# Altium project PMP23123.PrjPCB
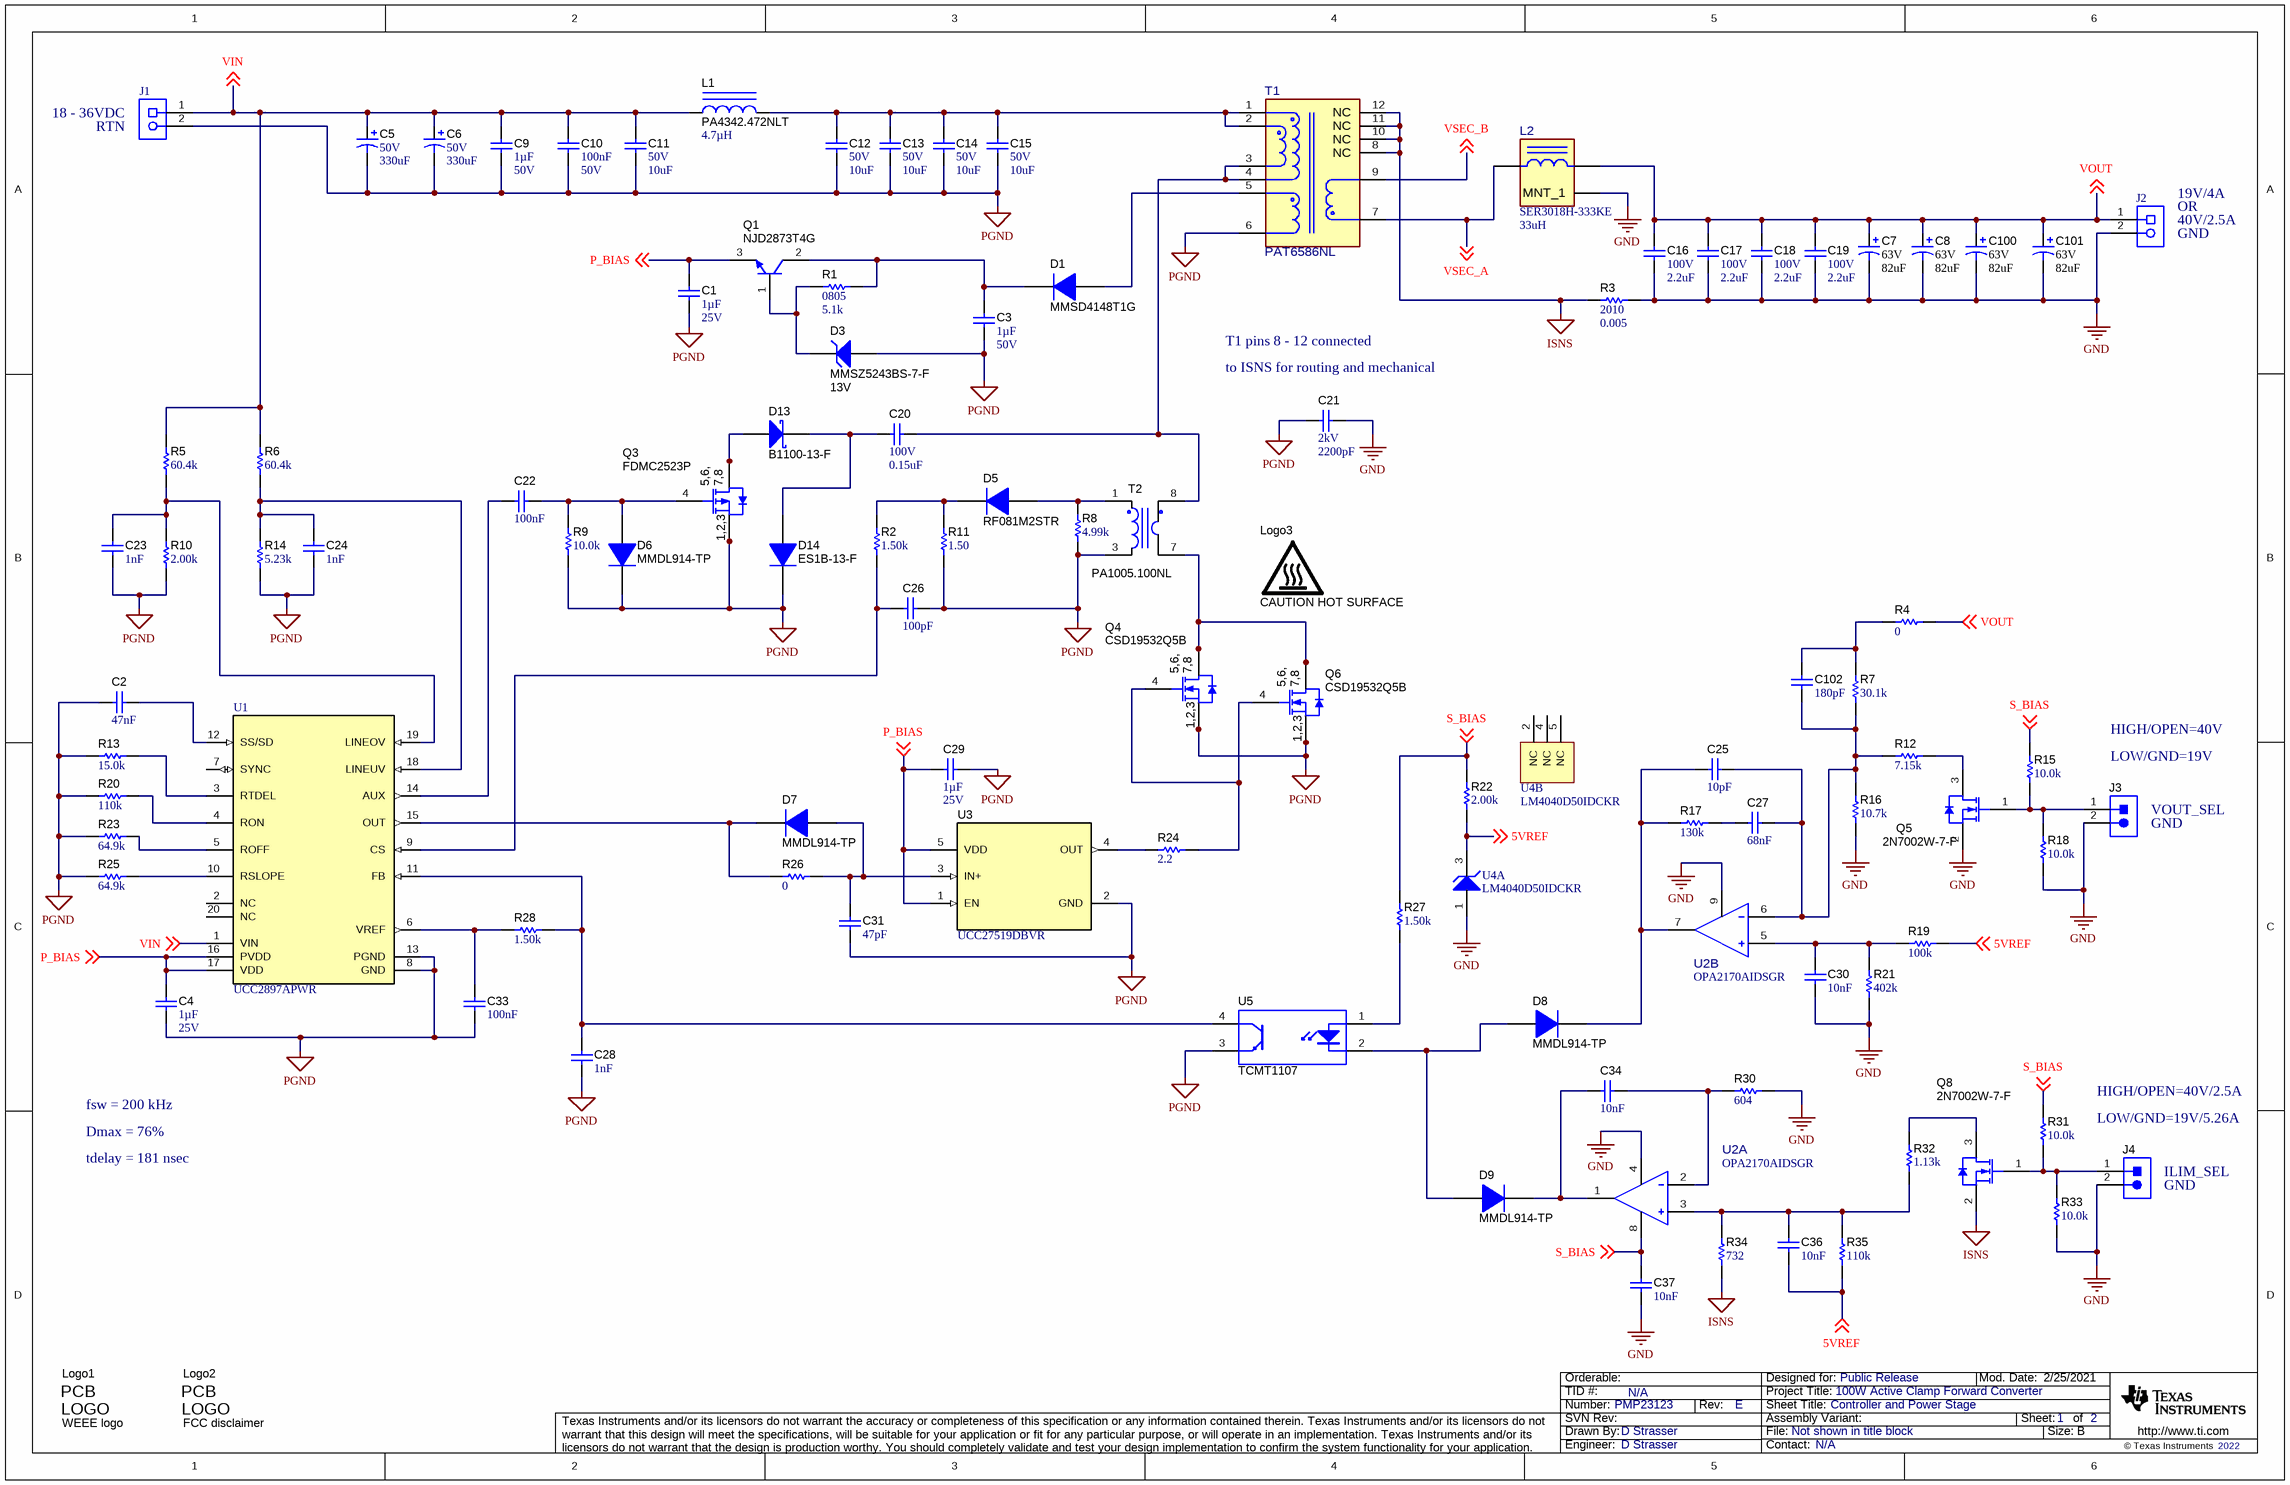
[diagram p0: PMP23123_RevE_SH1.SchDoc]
CopyrightYear: 2022; PCB_Layout: D Strasser; PCB_Rev: E; PRJ_Customer: Public Release; PRJ_Engineer: D Strasser; PRJ_Number: PMP23123; PRJ_Title: 100W Active Clamp Forward Converter; SCH_Rev: E; TechSupport: N/A; TID: N/A
2 sheets, 128 parts. Net scope: global (net labels, ports and power ports of the same name join across sheets).
Board file: PMP23123_RevE.PcbDoc
Sheets:
  PMP23123_RevE_SH1.SchDoc
  PMP23123_RevE_SH2.SchDoc

## Sheet PMP23123_RevE_SH1.SchDoc: Controller and Power Stage
size 431 x 279 mm; Date: Not shown in title block; ApprovedBy: Not shown in title block; CheckedBy: Not shown in title block; Author: Not shown in title block; CompanyName: Not shown in title block; DrawnBy: D Strasser; Engineer: Not shown in title block; Organization: Not shown in title block; Address1: Not shown in title block; Address2: Not shown in title block; Address3: Not shown in title block; Address4: Not shown in title block; DocumentNumber: 1; Revision: Use project parameter SCH_Rev; SheetNumber: 1; SheetTotal: 2; PageSetup: Record=PageOptions¦CenterHorizontal=True¦CenterVertical=True¦PrintScale=1.00¦XCorrection=1.00¦YCorrection=1.00¦PrintKind=0¦BorderSize=5000000¦LeftOffset=0¦BottomOffset=0¦Orientation=2¦PaperLength=1000¦PaperWidth=1000¦Scale=100¦PaperSource=15¦PrintQuality=600¦MediaType=1¦DitherType=10¦PaperKind=Letter¦PrintScaleMode=1

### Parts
C1  Cap_F: 1µF  VDC_V: 25V  [0603L]  (hidden comment: C0603C105K3RACTU)
C2  Cap_F: 47nF  [0603L]  (hidden comment: GRM188R71E473KA01D)
C3  Cap_F: 1µF  VDC_V: 50V  [0805_HV]  (hidden comment: C0805C105K5RACTU)
C4  Cap_F: 1µF  VDC_V: 25V  [0603L]  (hidden comment: C0603C105K3RACTU)
C5  VDC_V: 50V  ValueDisplayed: 330uF  [SM_RADIAL_H13]  (hidden comment: EEV-FK1H331Q)
C6  VDC_V: 50V  ValueDisplayed: 330uF  [SM_RADIAL_H13]  (hidden comment: EEV-FK1H331Q)
C7  VDC_V: 63V  ValueDisplayed: 82uF  [SM_RADIAL_10BMM]  (hidden comment: HHXD630ARA820MJA0G)
C8  VDC_V: 63V  ValueDisplayed: 82uF  [SM_RADIAL_10BMM]  (hidden comment: HHXD630ARA820MJA0G)
C9  Cap_F: 1µF  VDC_V: 50V  [0805_HV]  (hidden comment: C0805C105K5RACTU)
C10  Cap_F: 100nF  VDC_V: 50V  [0603]  (hidden comment: C0603C104K5RACTU)
C11  VDC_V: 50V  ValueDisplayed: 10uF  [1210_280]  (hidden comment: UMK325AB7106KM-T)
C12  VDC_V: 50V  ValueDisplayed: 10uF  [1210_280]  (hidden comment: UMK325AB7106KM-T)
C13  VDC_V: 50V  ValueDisplayed: 10uF  [1210_280]  (hidden comment: UMK325AB7106KM-T)
C14  VDC_V: 50V  ValueDisplayed: 10uF  [1210_280]  (hidden comment: UMK325AB7106KM-T)
C15  VDC_V: 50V  ValueDisplayed: 10uF  [1210_280]  (hidden comment: UMK325AB7106KM-T)
C16  VDC_V: 100V  ValueDisplayed: 2.2uF  [1210_210]  (hidden comment: C1210C225K1RACTU)
C17  VDC_V: 100V  ValueDisplayed: 2.2uF  [1210_210]  (hidden comment: C1210C225K1RACTU)
C18  VDC_V: 100V  ValueDisplayed: 2.2uF  [1210_210]  (hidden comment: C1210C225K1RACTU)
C19  VDC_V: 100V  ValueDisplayed: 2.2uF  [1210_210]  (hidden comment: C1210C225K1RACTU)
C20  VDC_V: 100V  ValueDisplayed: 0.15uF  [1206]  (hidden comment: GRM31MR72A154KA01L)
C21  VDC_V: 2kV  ValueDisplayed: 2200pF  [1812_HV]  (hidden comment: C4532X7R3D222K130KA)
C22  Cap_F: 100nF  [0603L]  (hidden comment: 885012206071)
C23  Cap_F: 1nF  [0603L]  (hidden comment: 885012206083)
C24  Cap_F: 1nF  [0603L]  (hidden comment: 885012206083)
C25  ValueDisplayed: 10pF  [0603L]  (hidden comment: C0603C100J5GACTU)
C26  ValueDisplayed: 100pF  [0603]  (hidden comment: 885012006057)
C27  Cap_F: 68nF  [0603L]  (hidden comment: 885012206070)
C28  Cap_F: 1nF  [0603L]  (hidden comment: 885012206083)
C29  Cap_F: 1µF  VDC_V: 25V  [0603L]  (hidden comment: C0603C105K3RACTU)
C30  Cap_F: 10nF  [0603L]  (hidden comment: C0603C103K5RACTU)
C31  ValueDisplayed: 47pF  [0603L]  (hidden comment: C0603C470J5GACTU)
C33  Cap_F: 100nF  [0603L]  (hidden comment: 885012206071)
C34  Cap_F: 10nF  [0603L]  (hidden comment: C0603C103K5RACTU)
C36  Cap_F: 10nF  [0603L]  (hidden comment: C0603C103K5RACTU)
C37  Cap_F: 10nF  [0603L]  (hidden comment: C0603C103K5RACTU)
C100  VDC_V: 63V  ValueDisplayed: 82uF  [SM_RADIAL_10BMM]  (hidden comment: HHXD630ARA820MJA0G)
C101  VDC_V: 63V  ValueDisplayed: 82uF  [SM_RADIAL_10BMM]  (hidden comment: HHXD630ARA820MJA0G)
C102  ValueDisplayed: 180pF  [0603L]  (hidden comment: C0603C181J5GACTU)
D1  MMSD4148T1G  [SOD-123]
D3  MMSZ5243BS-7-F  value 13V  [SOD-323]
D5  RF081M2STR  [SOD-123]
D6  MMDL914-TP  [SOD-323]
D7  MMDL914-TP  [SOD-323]
D8  MMDL914-TP  [SOD-323]
D9  MMDL914-TP  [SOD-323]
D13  B1100-13-F  [SMA]
D14  ES1B-13-F  [SMA]
J1  691236510002  [Wurth_691236510002]  (value not drawn)
J2  691236510002  [Wurth_691236510002]  (value not drawn)
J3  TSW-102-07-G-S  [TSW-102-07-G-S]  (value not drawn)
J4  TSW-102-07-G-S  [TSW-102-07-G-S]  (value not drawn)
L1  PA4342.472NLT  ValueDisplayed: 4.7µH  [PA4342_2]
L2  value 33uH  [FP-SER3018H-333KE_SMT3_27MM94_27MM94-MFG]  (hidden comment: SER3018H-333KE)
Logo1  WEEE logo  [WEEE_Minimum]  (no BOM)
Logo2  FCC disclaimer  [FCC_disclaimer]  (no BOM)
Logo3  CAUTION HOT SURFACE  [IEC_HotSurface_Small]  (no BOM)
Q1  NJD2873T4G  [DPAK]
Q3  FDMC2523P  [MLP08S]
Q4  CSD19532Q5B  [DNK0008A]
Q5  2N7002W-7-F  [SOT-323]
Q6  CSD19532Q5B  [DNK0008A]
Q8  2N7002W-7-F  [SOT-323]
R1  PackageReference: 0805  ValueDisplayed: 5.1k  [0805_HV]  (hidden comment: CRCW08055K10JNEA)
R2  ValueDisplayed: 1.50k  [0603L]  (hidden comment: CRCW06031K50FKEA)
R3  ValueDisplayed: 0.005  [2010]  (hidden comment: WSL20105L000FEA)
R4  ValueDisplayed: 0  [0603L]  (hidden comment: CRCW06030000Z0EA)
R5  ValueDisplayed: 60.4k  [0603L]  (hidden comment: CRCW060360K4FKEA)
R6  ValueDisplayed: 60.4k  [0603L]  (hidden comment: CRCW060360K4FKEA)
R7  ValueDisplayed: 30.1k  [0603L]  (hidden comment: CRCW060330K1FKEA)
R8  ValueDisplayed: 4.99k  [0603L]  (hidden comment: CRCW06034K99FKEA)
R9  ValueDisplayed: 10.0k  [0603L]  (hidden comment: CRCW060310K0FKEA)
R10  ValueDisplayed: 2.00k  [0603L]  (hidden comment: CRCW06032K00FKEA)
R11  ValueDisplayed: 1.50  [0603L]  (hidden comment: CRCW06031R50FKEA)
R12  ValueDisplayed: 7.15k  [0603L]  (hidden comment: CRCW06037K15FKEA)
R13  ValueDisplayed: 15.0k  [0603L]  (hidden comment: CRCW060315K0FKEA)
R14  ValueDisplayed: 5.23k  [0603L]  (hidden comment: CRCW06035K23FKEA)
R15  ValueDisplayed: 10.0k  [0603L]  (hidden comment: CRCW060310K0FKEA)
R16  ValueDisplayed: 10.7k  [0603L]  (hidden comment: CRCW060310K7FKEA)
R17  ValueDisplayed: 130k  [0603L]  (hidden comment: CRCW0603130KFKEA)
R18  ValueDisplayed: 10.0k  [0603L]  (hidden comment: CRCW060310K0FKEA)
R19  ValueDisplayed: 100k  [0603L]  (hidden comment: CRCW0603100KFKEA)
R20  ValueDisplayed: 110k  [0603L]  (hidden comment: CRCW0603110KFKEA)
R21  ValueDisplayed: 402k  [0603L]  (hidden comment: CRCW0603402KFKEA)
R22  ValueDisplayed: 2.00k  [0603L]  (hidden comment: CRCW06032K00FKEA)
R23  ValueDisplayed: 64.9k  [0603L]  (hidden comment: CRCW060364K9FKEA)
R24  ValueDisplayed: 2.2  [0603L]  (hidden comment: CRCW06032R20JNEA)
R25  ValueDisplayed: 64.9k  [0603L]  (hidden comment: CRCW060364K9FKEA)
R26  ValueDisplayed: 0  [0603L]  (hidden comment: CRCW06030000Z0EA)
R27  ValueDisplayed: 1.50k  [0603L]  (hidden comment: CRCW06031K50FKEA)
R28  ValueDisplayed: 1.50k  [0603L]  (hidden comment: CRCW06031K50FKEA)
R30  ValueDisplayed: 604  [0603L]  (hidden comment: CRCW0603604RFKEA)
R31  ValueDisplayed: 10.0k  [0603L]  (hidden comment: CRCW060310K0FKEA)
R32  ValueDisplayed: 1.13k  [0603L]  (hidden comment: CRCW06031K13FKEA)
R33  ValueDisplayed: 10.0k  [0603L]  (hidden comment: CRCW060310K0FKEA)
R34  ValueDisplayed: 732  [0603L]  (hidden comment: CRCW0603732RFKEA)
R35  ValueDisplayed: 110k  [0603L]  (hidden comment: CRCW0603110KFKEA)
T1  PAT6586NL  [FP-PAT6586NL_SMT_XFRMR_27MM1_26MM42-MFG]
T2  PA1005.100NL  [P82xx]
U1  UCC2897APWR  [PW0020A_N]
U2  OPA2170AIDSGR  [DSG0008A-MFG]  (parts A,B of 2)
U3  UCC27519DBVR  [DBV0005A_N]
U4  LM4040D50IDCKR  [DCK0005A_N]  (parts A,B of 2)
U5  TCMT1107  [SOP-4]

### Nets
GND: C7.2(-) C8.2(-) C16.1 C17.1 C18.1 C19.1 C21.1 C30.2 C37.1 C100.2(-) C101.2(-) J2.2 J3.2 J4.2 L2.1(MNT_1) Q5.2(S) R3.2 R16.2 R18.2 R21.2 R30.2 R33.2 U2.4(V-) U2.9(Thermal_Pad) U4.1(ANODE)
ISNS: Q8.2(S) R3.1 R34.2 T1.8(NC) T1.10(NC) T1.11(NC) T1.12(NC)
PGND: C1.1 C2.2 C3.1 C4.1 C5.2(-) C6.2(-) C9.1 C10.1 C11.1 C12.1 C13.1 C14.1 C15.1 C21.2 C23.1 C24.1 C26.1 C28.1 C29.2 C31.2 C33.1 D3.2(A) D6.1(K) D14.1(K) J1.2 Q3.1(S) Q3.2(S) Q3.3(S) Q4.1(S) Q4.2(S) Q4.3(S) Q6.1(S) Q6.2(S) Q6.3(S) R8.1 R9.2 R10.2 R11.2 R13.2 R14.2 R20.1 R23.1 R25.1 T1.6 T2.3 U1.8(GND) U1.13(PGND) U3.2(GND) U5.3(E)
5VREF: C36.2 R19.2 R22.2 R35.1 U4.3(CATHODE) ; off-sheet 5VREF
P_BIAS: C1.2 C4.2 C29.1 Q1.3(E) U1.16(PVDD) U1.17(VDD) U3.1(EN) U3.5(VDD) ; off-sheet P_BIAS
S_BIAS: C37.2 R15.1 R22.1 R27.1 R31.1 U2.8(V+) ; off-sheet S_BIAS
VIN: C5.1(+) C6.1(+) C9.2 C10.2 C11.2 J1.1 L1.1 R5.2 R6.2 U1.1(VIN) ; off-sheet VIN
VOUT: C7.1(+) C8.1(+) C16.2 C17.2 C18.2 C19.2 C100.1(+) C101.1(+) J2.1 L2.3 R4.2 ; off-sheet VOUT
VSEC_A: L2.2 T1.7 ; off-sheet VSEC_A
VSEC_B: T1.9 ; off-sheet VSEC_B
NetC2_1: C2.1 U1.12(SS/SD)
NetC3_2: C3.2 D1.1(K) Q1.2(C) R1.2
NetC12_2: C12.2 C13.2 C14.2 C15.2 L1.2 T1.1 T1.2
NetC20_1: C20.1 T1.3 T1.4 T2.8
NetC20_2: C20.2 D13.1(K) D14.2(A)
NetC22_1: C22.1 D6.2(A) Q3.4(G) R9.1
NetC22_2: C22.2 U1.14(AUX)
NetC23_2: C23.2 R5.1 R10.1 U1.19(LINEOV)
NetC24_2: C24.2 R6.1 R14.1 U1.18(LINEUV)
NetC25_1: C25.1 C27.1 C102.1 R7.2 R12.1 R16.1 U2.6(-IN_B)
NetC25_2: C25.2 D8.1(K) R17.1 U2.7(OUT_B)
NetC26_2: C26.2 R2.2 U1.9(CS)
NetC27_2: C27.2 R17.2
NetC28_2: C28.2 R28.1 U1.11(FB) U5.4(C)
NetC30_1: C30.1 R19.1 R21.1 U2.5(+IN_B)
NetC31_1: C31.1 D7.2(A) R26.2 U3.3(IN+)
NetC33_2: C33.2 R28.2 U1.6(VREF)
NetC34_1: C34.1 R30.1 U2.2(-IN_A)
NetC34_2: C34.2 D9.1(K) U2.1(OUT_A)
NetC36_1: C36.1 R32.2 R34.1 R35.2 U2.3(+IN_A)
NetC102_2: C102.2 R4.1 R7.1
NetD1_2: D1.2(A) T1.5
NetD3_1: D3.1(K) Q1.1(B) R1.1
NetD5_1: D5.1(K) R2.1 R11.1
NetD5_2: D5.2(A) R8.2 T2.1
NetD7_1: D7.1(K) R26.1 U1.15(OUT)
NetD8_2: D8.2(A) D9.2(A) U5.2(K)
NetD13_2: D13.2(A) Q3.5(D) Q3.6(D) Q3.7(D) Q3.8(D)
NetJ3_1: J3.1 Q5.1(G) R15.2 R18.1
NetJ4_1: J4.1 Q8.1(G) R31.2 R33.1
NetQ4_4: Q4.4(G) Q6.4(G) R24.1
NetQ4_5: Q4.5(D) Q4.6(D) Q4.7(D) Q4.8(D) Q4.9(D) Q6.5(D) Q6.6(D) Q6.7(D) Q6.8(D) Q6.9(D) T2.7
NetQ5_3: Q5.3(D) R12.2
NetQ8_3: Q8.3(D) R32.1
NetR13_1: R13.1 U1.3(RTDEL)
NetR20_2: R20.2 U1.4(RON)
NetR23_2: R23.2 U1.5(ROFF)
NetR24_2: R24.2 U3.4(OUT)
NetR25_2: R25.2 U1.10(RSLOPE)
NetR27_2: R27.2 U5.1(A)

Not connected (* = marked no-connect by the designer): U1 2(NC) 7(SYNC) 20(NC); U4 2(NC) 4(NC) 5(NC)

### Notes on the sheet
- (near J1) 18 - 36VDC
- (near J1) RTN
- (near J2) 19V/4A
- (near J2) OR
- (near J2) 40V/2.5A
- (near J2) GND
- T1 pins 8 - 12 connected
- (near C21) to ISNS for routing and mechanical
- (near J3) LOW/GND=19V
- HIGH/OPEN=40V
- (near J3) GND
- (near J3) VOUT_SEL
- fsw = 200 kHz
- HIGH/OPEN=40V/2.5A
- Dmax = 76%
- tdelay = 181 nsec
- LOW/GND=19V/5.26A
- (near J4) ILIM_SEL
- (near J4) GND

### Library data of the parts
C1 C4 C29 = CMP-0006867-4: CAP, CERM, 1 uF, 25 V, +/- 10%, X7R, 0603; Manufacturer: Kemet; TaMin_C: -55°C; Polarized: N; SizeAreaWB_mm2: 4.68; Value1: Unknown; U/M: EA; Value: 1uF; TaMax_C: 125°C; SizeZ_mm: 1; SizeX_mm: 1.6; SizeY_mm: 0.8; Cap_Case: 0603; SizeArea_mm2: 1.28; AEC Category: Q200
C2 = CMP-0007423-5: CAP, CERM, 0.047 uF, 25 V, +/- 10%, X7R, 0603; Manufacturer: MuRata; Polarized: N; SizeArea_mm2: 1.28; Value2: 25V; Cap_Case: 0603; TaMax_C: 125°C; SizeZ_mm: 1; Value1: Unknown; SizeAreaWB_mm2: 4.68; TaMin_C: -55°C; AEC Category: Q200; SizeY_mm: 0.8; MFG_Status: TI_Obsolete; SizeX_mm: 1.6; U/M: EA
C3 C9 = CMP-0007730-2: CAP, CERM, 1 uF, 50 V, +/- 10%, X7R, 0805; Manufacturer: Kemet; TaMin_C: -55°C; Polarized: N; SizeAreaWB_mm2: 6.75; Value1: Unknown; U/M: EA; Value: 1uF; TaMax_C: 125°C; SizeZ_mm: 1.45; SizeX_mm: 2; SizeY_mm: 1.25; Cap_Case: 0805; SizeArea_mm2: 2.5; AEC Category: Q200
C5 C6 = CMP-0011211-2: CAP, AL, 330 uF, 50 V, +/- 20%, 0.12 ohm, AEC-Q200 Grade 2, SMD; Manufacturer: Panasonic; TaMin_C: -55°C; ESR_ohm: 0.12; Polarized: Y; SizeAreaWB_mm2: 263.5; U/M: EA; Value: 330uF; TaMax_C: 105°C; SizeZ_mm: 13.5; SizeX_mm: 15; Cap_Case: H13; SizeArea_mm2: 202.5; CompType: Capacitor; Cap_F: 330µF; IRMS_A: 900mA; AEC Grade: 2; AEC Category: Q200
C7 C8 C100 C101 = CMP-0012603-3: CAP, Polymer Hybrid, 82 uF, 63 V, +/- 20%, 30 ohm, 10x10 SMD; Manufacturer: United Chem-Con; TaMin_C: -55°C; ESR_ohm: 30; Polarized: Y; SizeAreaWB_mm2: 159.9; Value1: 30 ohm; Value: 82uF; TaMax_C: 125°C; SizeZ_mm: 10.2; SizeX_mm: 11; SizeY_mm: 10.3; SizeArea_mm2: 113.3; CompType: Capacitor; Cap_F: 82µF; IRMS_A: 2.4A; AEC Category: Q200
C10 = CMP-0006861-4: CAP, CERM, 0.1 uF, 50 V, +/- 10%, X7R, 0603; Manufacturer: Kemet; TaMin_C: -55°C; Polarized: N; SizeAreaWB_mm2: 4.68; Value1: Unknown; U/M: EA; Value: 0.1uF; TaMax_C: 125°C; SizeZ_mm: 1; SizeX_mm: 1.6; SizeY_mm: 0.8; SizeArea_mm2: 1.28; AEC Category: Q200
C11-C15 = CMP-0009259-2: CAP, CERM, 10 uF, 50 V, +/- 10%, X7R, 1210; Manufacturer: Taiyo Yuden; TaMin_C: -55°C; Polarized: N; SizeAreaWB_mm2: 14.7; Value1: Unknown; U/M: EA; Value: 10uF; TaMax_C: 125°C; SizeZ_mm: 2.8; SizeX_mm: 3.2; SizeY_mm: 2.5; Cap_Case: 1210; SizeArea_mm2: 8; Cap_F: 10µF; AEC Category: Q200
C16-C19 = CMP-0009084-1: CAP, CERM, 2.2 uF, 100 V, +/- 10%, X7R, 1210; Manufacturer: Kemet; TaMin_C: -55°C; Polarized: N; SizeAreaWB_mm2: 14.7; Value1: Unknown; U/M: EA; Value: 2.2uF; TaMax_C: 125°C; SizeZ_mm: 2.1; SizeX_mm: 3.2; SizeY_mm: 2.5; Cap_Case: 1210; SizeArea_mm2: 8; Cap_F: 2.2µF; AEC Category: Q200
C20 = CMP-0008999-2: CAP, CERM, 0.15 uF, 100 V, +/- 10%, X7R, 1206; Manufacturer: MuRata; TaMin_C: -55°C; Polarized: N; SizeAreaWB_mm2: 10.92; Value1: Unknown; U/M: EA; Value: 0.15uF; TaMax_C: 125°C; SizeZ_mm: 1.35; SizeX_mm: 3.2; SizeY_mm: 1.6; Cap_Case: 0805; SizeArea_mm2: 5.12; Cap_F: 150nF; AEC Category: Q200
C21 = CMP-0009358-2: CAP, CERM, 2200 pF, 2000 V, +/- 10%, X7R, 1812; Manufacturer: TDK; TaMin_C: -55°C; Polarized: N; SizeAreaWB_mm2: 23.1; Value1: Unknown; U/M: EA; Value: 2200pF; TaMax_C: 125°C; SizeZ_mm: 1.35; SizeX_mm: 4.5; SizeY_mm: 3.2; Cap_Case: 1812; Value2: 2000V; SizeArea_mm2: 14.4; Cap_F: 2.2nF; AEC Category: Q200
C22 C33 = CMP-0006832-5: CAP, CERM, 0.1 uF, 25 V, +/- 10%, X7R, 0603; Manufacturer: Wurth Elektronik; TaMin_C: -55°C; Polarized: N; SizeAreaWB_mm2: 4.68; Value1: Unknown; U/M: EA; Value: 0.1uF; TaMax_C: 125°C; SizeZ_mm: 1; SizeX_mm: 1.6; SizeY_mm: 0.8; Cap_Case: 0603; Value2: 25V; SizeArea_mm2: 1.28; AEC Category: Q200
C23 C24 C28 = CMP-0064933-4: CAP, CERM, 1000 pF, 50 V,+/- 10%, X7R, 0603; Manufacturer: Wurth Elektronik; TaMin_C: -55°C; Polarized: N; SizeAreaWB_mm2: 4.68; Value1: Unknown; U/M: EA; Value: 1000pF; TaMax_C: 125°C; SizeZ_mm: 1; SizeX_mm: 1.6; SizeY_mm: 0.8; Cap_Case: 0603; Value2: 50V; SizeArea_mm2: 1.28; AEC Category: Q200
C25 = CMP-0006839-4: CAP, CERM, 10 pF, 50 V, +/- 5%, C0G/NP0, 0603; Manufacturer: Kemet; TaMin_C: -55°C; Polarized: N; SizeAreaWB_mm2: 4.68; Value1: Unknown; U/M: EA; Value: 10pF; TaMax_C: 125°C; SizeZ_mm: 1; SizeX_mm: 1.6; SizeY_mm: 0.8; Cap_Case: 0603; Value2: 50V; SizeArea_mm2: 1.28; AEC Category: Q200
C26 = CMP-0006822-4: CAP, CERM, 100 pF, 50 V, +/- 5%, C0G/NP0, 0603; Manufacturer: Wurth Elektronik; TaMin_C: -55°C; Polarized: N; SizeAreaWB_mm2: 4.68; Value1: Unknown; U/M: EA; Value: 100pF; TaMax_C: 125°C; SizeZ_mm: 1; SizeX_mm: 1.6; SizeY_mm: 0.8; Value2: 50V; SizeArea_mm2: 1.28; AEC Category: Q200
C27 = CMP-0750069-1: CAP, CERM, 0.068 µF, 25 V,+/- 10%, X7R, 0603; Manufacturer: Wurth Elektronik; SizeAreaWB_mm2: 4.68; Cap_Case: 0603; U/M: EA; SizeArea_mm2: 1.28; TaMin_C: -55°C; Value: 0.068uF; SizeY_mm: 0.8; SizeX_mm: 1.6; AEC Category: Q200; VDC_V: 25V; AEC Qualified: N; SizeZ_mm: 1; TaMax_C: 125°C
C30 C34 C36 C37 = CMP-0006854-4: CAP, CERM, 0.01 uF, 50 V, +/- 10%, X7R, 0603; Manufacturer: Kemet; TaMin_C: -55°C; Polarized: N; SizeAreaWB_mm2: 4.68; Value1: Unknown; U/M: EA; Value: 0.01uF; TaMax_C: 125°C; SizeZ_mm: 1; SizeX_mm: 1.6; SizeY_mm: 0.8; Cap_Case: 0603; Value2: 50V; SizeArea_mm2: 1.28; AEC Category: Q200
C31 = CMP-0006939-4: CAP, CERM, 47 pF, 50 V, +/- 5%, C0G/NP0, 0603; Manufacturer: Kemet; TaMin_C: -55°C; Polarized: N; SizeAreaWB_mm2: 4.68; Value1: Unknown; U/M: EA; Value: 47pF; TaMax_C: 125°C; SizeZ_mm: 1; SizeX_mm: 1.6; SizeY_mm: 0.8; Cap_Case: 0603; Value2: 50V; SizeArea_mm2: 1.28; AEC Category: Q200
C102 = CMP-0006888-4: CAP, CERM, 180 pF, 50 V, +/- 5%, C0G/NP0, 0603; Manufacturer: Kemet; TaMin_C: -55°C; Polarized: N; SizeAreaWB_mm2: 4.68; Value1: Unknown; U/M: EA; Value: 180pF; TaMax_C: 125°C; SizeZ_mm: 1; SizeX_mm: 1.6; SizeY_mm: 0.8; Cap_Case: 0603; Value2: 50V; SizeArea_mm2: 1.28; AEC Category: Q200
D1 = CMP-0029032-2: Diode, Switching, 100 V, 0.2 A, SOD-123; Manufacturer: ON Semiconductor; Value: 100V; SizeY_mm: 1.7; Io_A: 200mA; SizeAreaWB_mm2: 13.095; SizeArea_mm2: 6.545; Vf_V: 1V; TJmax_C: 150°C; SizeX_mm: 3.85; SizeZ_mm: 1.35; Value1: 0.2A; Green_Lifecycle: Active; AEC Category: Q101; Green_REACh: Passed
D3 = CMP-0005832-4: Diode, Zener, 13 V, 200 mW, SOD-323; Manufacturer: Diodes Inc.; SizeX_mm: 2.7; RJA_CperW: 350; SizeY_mm: 1.35; Value1: 0.2W; AEC Category: Q101; Power_W: 200mW; SizeZ_mm: 1; SizeArea_mm2: 3.645; SizeAreaWB_mm2: 8.695
D5 = CMP-0076993-2: Diode, Fast Rectifier, 200 V, 0.8 A, SOD-123; Manufacturer: Rohm; Value: 200V; AEC Category: Q101; SizeAreaWB_mm2: 13.095; Value1: 0.8A; SizeY_mm: 1.7; SizeZ_mm: 1.35; Green_REACh: Incomplete; Green_Lifecycle: Not Set; Io_A: 800mA; SizeX_mm: 3.85; SizeArea_mm2: 6.545; TJmax_C: 150°C; Vf_V: 950mV; Value2: 0.95V
D6-D9 = CMP-0029045-2: Diode, Switching, 100 V, 0.2 A, SOD-323; Manufacturer: Micro Commercial Components; Value: 100V; TJmax_C: 150°C; Vf_V: 1V; Value1: 0.2A; SizeArea_mm2: 3.645; SizeZ_mm: 1; Green_Lifecycle: Not Set; SizeY_mm: 1.35; Green_REACh: Incomplete; SizeAreaWB_mm2: 8.695; SizeX_mm: 2.7; Io_A: 200mA; AEC Category: Q101
D13 = CMP-0028371-2: Diode, Schottky, 100 V, 1 A, SMA; Manufacturer: Diodes Inc.; Io_A: 1A; SizeZ_mm: 2.87; Green_REACh: Passed; TJmax_C: 150°C; Value: 100V; SizeAreaWB_mm2: 37.3428; Vf_V: 790mV; RJC_CperW: 25; SizeX_mm: 5.59; AEC Category: Q101; SizeArea_mm2: 16.3228; SizeY_mm: 2.92; Value2: 0.79V; Green_Lifecycle: Active
D14 = CMP-0029022-2: Diode, Superfast Rectifier, 100 V, 1 A, SMA; Manufacturer: Diodes Inc.; Io_A: 1A; TJmax_C: 150°C; Value: 100V; Vf_V: 920mV; RJC_CperW: 25; SizeZ_mm: 2.87; SizeX_mm: 5.59; AEC Category: Q101; Value2: 0.92V; SizeArea_mm2: 16.3228; Green_REACh: Incomplete; SizeY_mm: 2.92; SizeAreaWB_mm2: 37.3428; Green_Lifecycle: Not Set
J1 J2 = CMP-0079044-1: Terminal Block, 5.08mm, 2x1, R/A, TH; Manufacturer: Wurth Elektronik; Pitch_mm: 5.08; Cert_VDE: Y; Gender: Female; Voltage_V: 300V; Current_A: 20A; Row_Count: 1
J3 J4 = CMP-0075405-3: Header, 100mil, 2x1, Gold, TH; Manufacturer: Samtec; Current_A: 6.3A; Green_Lifecycle: Active; Pitch_mm: 2.54; Cert_CSA: Y; Cert_VDE: N; Green_REACh: Passed; Row_Count: 1; Gender: Male; Voltage_V: 550V
L1 = CMP-0079793-1: Inductor, Shielded, 4.7 µH, 10 A, 0.0155 ohm, AEC-Q200 Grade 1, SMD; Manufacturer: Pulse Engineering; SizeAreaWB_mm2: 166.05; Irms: 10A @ 40C rise; SizeArea_mm2: 118.45; AEC Qualified: Y; AEC Category: Q200; Value: 4.7uH; SizeZ_mm: 4; Imax_A: 10A; AEC Grade: 1; SizeY_mm: 10.3; Isat: 17A @ 30% inductance drop; DCR_ohm: 15.5m; SizeX_mm: 11.5
L2 = CMP-0095492-1: Shielded Power Inductors 33uH 10% 2.82mOhm 28A; Manufacturer: Coilcraft; TaMin_C: -40°C; Isat: 7A; Self Resonant Frequency: 10MHz; Material: Ferrite; SizeZ_mm: 17.78mm; Ind_H: 33µH; Shrouded: true; DCR_ohm: 2.82m; Test Frequency: 500kHz; TaMax_C: +85°C; AEC Qualified: No
Logo1 = CMP-0074769-1
Logo2 = CMP-0074847-1: FCC_disclaimer
Logo3 = CMP-0074837-2: IEC 61010-1 Hot Surface Warning; Manufacturer: Texas Instruments; CompType: IC; AEC Category: Q200; SymbolCreator: a0412235
Q1 = CMP-0000481-4: Transistor, NPN, 50 V, 2 A, AEC-Q101, DPAK; Manufacturer: ON Semiconductor; SizeX_mm: 9.91; HfeMax: 360; NPN: 1; TaMin_C: -65°C; Vcesat1_V: 300mV; SizeY_mm: 6.54; CompType: BJT; PNP: 0; Vceo_V: 50V; SizeAreaWB_mm2: 101.7114; SizeZ_mm: 2.29; Value: 50 V; AEC Qualified: Y; IcRated_A: 2A; TaMax_C: 175°C; Value1: 2 A; SizeArea_mm2: 64.8114; AEC Category: Q101
Q3 = CMP-0000056-3: MOSFET, P-CH, -150 V, -3 A, QFN-8; Alternate Manufacturer: None; Manufacturer: Fairchild Semiconductor; ChType: P; VdsMax_V: -150V; AEC Category: Q101; Value2: 6.2 nC; SizeAreaWB_mm2: 18.49; QgTyp_nC: 6.2; Value: -150V; SizeZ_mm: 0.8; ChMode: Enhancement; AEC Qualified: N; IdsMax_A: -3A; SizeX_mm: 3.3; SizeArea_mm2: 10.89; Vgs_V: -30V
Q4 Q6 = CMP-0000958-3: MOSFET, N-CH, 100 V, 17 A, DNK0008A (VSON-CLIP-8); Alternate Manufacturer: None; Manufacturer: Texas Instruments; SizeZ_mm: 1; ChType: N; Value2: 48 nC; VdsMax_V: 100V; SizeX_mm: 6; SizeY_mm: 5; Vgs_V: 20V; QgTyp_nC: 48; Value: 100V; SizeArea_mm2: 30; AEC Category: Q101; IdsMax_A: 17A; SizeAreaWB_mm2: 56; U/M: EA
Q5 Q8 = CMP-0000776-1: MOSFET, N-CH, 60 V, 0.115 A, SOT-323; Alternate Manufacturer: None; Manufacturer: Diodes Inc.; SizeZ_mm: 1.1; ChType: N; Value1: 7; VdsMax_V: 60V; SizeX_mm: 2.2; Vgs_V: 20V; Value: 60V; Rdson45_ohm: 7.5; SizeArea_mm2: 4.84; AEC Category: Q101; IdsMax_A: 115mA; SizeAreaWB_mm2: 10.24; U/M: EA
R1 = CMP-0020572-3: RES, 5.1 k, 5%, 0.125 W, AEC-Q200 Grade 0, 0805; Manufacturer: Vishay-Dale; Power_W: 125mW; TempCo: 200 ppm/C; Value_Code: 5k10; Value: 5.1k; EIA_Code: E24; SizeX_mm: 2; SizeY_mm: 1.25; SizeZ_mm: 1.45; Value2: 0.125W; SizeArea_mm2: 2.5; AEC Qualified: Y; VDC_V: 150V; AEC Category: Q200; AEC Grade: 0
R2 R27 R28 = CMP-0022126-4: RES, 1.50 k, 1%, 0.1 W, AEC-Q200 Grade 0, 0603; Manufacturer: Vishay-Dale; Power_W: 100mW; TempCo: 100 ppm/C; Value_Code: 1k50; Value: 1.50k; EIA_Code: E96; Res_ohm: 1.5k; SizeX_mm: 1.6; SizeY_mm: 0.8; SizeZ_mm: 1; Value2: 0.1W; SizeArea_mm2: 1.28; AEC Qualified: Y; VDC_V: 75V; AEC Category: Q200; AEC Grade: 0
R3 = CMP-0016551-2: RES, 0.005, 1%, 0.5 W, 2010; Manufacturer: Vishay-Dale; Power_W: 500mW; TempCo: 110 ppm/C; Value_Code: 5L000; U/M: EA; Value: 0.005; EIA_Code: E96; Res_ohm: 5m; SizeX_mm: 5; SizeY_mm: 2.5; SizeZ_mm: 1.66; Value2: 0.5W; SizeArea_mm2: 12.5; AEC Category: Q200
R4 R26 = CMP-0025697-4: RES, 0, 5%, 0.1 W, AEC-Q200 Grade 0, 0603; Manufacturer: Vishay-Dale; Power_W: 100mW; TempCo: 200 ppm/C; Value_Code: 0000; Value: 0; EIA_Code: E24; SizeX_mm: 1.6; SizeY_mm: 0.8; SizeZ_mm: 1; Value2: 0.1W; SizeArea_mm2: 1.28; AEC Qualified: Y; VDC_V: 75V; AEC Category: Q200
R5 R6 = CMP-0022532-4: RES, 60.4 k, 1%, 0.1 W, AEC-Q200 Grade 0, 0603; Manufacturer: Vishay-Dale; Power_W: 100mW; TempCo: 100 ppm/C; Value_Code: 60k4; Value: 60.4k; EIA_Code: E96; SizeX_mm: 1.6; SizeY_mm: 0.8; SizeZ_mm: 1; Value2: 0.1W; SizeArea_mm2: 1.28; AEC Qualified: Y; VDC_V: 75V; AEC Category: Q200; AEC Grade: 0
R7 = CMP-0022324-4: RES, 30.1 k, 1%, 0.1 W, AEC-Q200 Grade 0, 0603; Manufacturer: Vishay-Dale; Power_W: 100mW; TempCo: 100 ppm/C; Value_Code: 30k1; Value: 30.1k; EIA_Code: E96; SizeX_mm: 1.6; SizeY_mm: 0.8; SizeZ_mm: 1; Value2: 0.1W; SizeArea_mm2: 1.28; AEC Qualified: Y; VDC_V: 75V; AEC Category: Q200; AEC Grade: 0
R8 = CMP-0022458-4: RES, 4.99 k, 1%, 0.1 W, AEC-Q200 Grade 0, 0603; Manufacturer: Vishay-Dale; Power_W: 100mW; TempCo: 100 ppm/C; Value_Code: 4k99; Value: 4.99k; EIA_Code: E96; SizeX_mm: 1.6; SizeY_mm: 0.8; SizeZ_mm: 1; Value2: 0.1W; SizeArea_mm2: 1.28; AEC Qualified: Y; VDC_V: 75V; AEC Category: Q200; AEC Grade: 0
R9 R15 R18 R31 R33 = CMP-0021998-4: RES, 10.0 k, 1%, 0.1 W, AEC-Q200 Grade 0, 0603; Manufacturer: Vishay-Dale; Power_W: 100mW; TempCo: 100 ppm/C; Value_Code: 10k0; Value: 10.0k; EIA_Code: E96; Res_ohm: 10k; SizeX_mm: 1.6; SizeY_mm: 0.8; SizeZ_mm: 1; Value2: 0.1W; SizeArea_mm2: 1.28; AEC Qualified: Y; VDC_V: 75V; AEC Category: Q200; AEC Grade: 0
R10 R22 = CMP-0022268-4: RES, 2.00 k, 1%, 0.1 W, AEC-Q200 Grade 0, 0603; Manufacturer: Vishay-Dale; Power_W: 100mW; TempCo: 100 ppm/C; Value_Code: 2k00; Value: 2.00k; EIA_Code: E96; Res_ohm: 2k; SizeX_mm: 1.6; SizeY_mm: 0.8; SizeZ_mm: 1; Value2: 0.1W; SizeArea_mm2: 1.28; AEC Qualified: Y; VDC_V: 75V; AEC Category: Q200; AEC Grade: 0
R11 = CMP-0022187-4: RES, 1.50, 1%, 0.1 W, AEC-Q200 Grade 0, 0603; Manufacturer: Vishay-Dale; Power_W: 100mW; TempCo: 100 ppm/C; Value_Code: 1R50; Value: 1.50; EIA_Code: E96; Res_ohm: 1.5; SizeX_mm: 1.6; SizeY_mm: 0.8; SizeZ_mm: 1; Value2: 0.1W; SizeArea_mm2: 1.28; AEC Qualified: Y; VDC_V: 75V; AEC Category: Q200; AEC Grade: 0
R12 = CMP-0022599-4: RES, 7.15 k, 1%, 0.1 W, AEC-Q200 Grade 0, 0603; Manufacturer: Vishay-Dale; Power_W: 100mW; TempCo: 100 ppm/C; Value_Code: 7k15; Value: 7.15k; EIA_Code: E96; SizeX_mm: 1.6; SizeY_mm: 0.8; SizeZ_mm: 1; Value2: 0.1W; SizeArea_mm2: 1.28; AEC Qualified: Y; VDC_V: 75V; AEC Category: Q200; AEC Grade: 0
R13 = CMP-0022066-4: RES, 15.0 k, 1%, 0.1 W, AEC-Q200 Grade 0, 0603; Manufacturer: Vishay-Dale; Power_W: 100mW; TempCo: 100 ppm/C; Value_Code: 15k0; Value: 15.0k; EIA_Code: E96; Res_ohm: 15k; SizeX_mm: 1.6; SizeY_mm: 0.8; SizeZ_mm: 1; Value2: 0.1W; SizeArea_mm2: 1.28; AEC Qualified: Y; VDC_V: 75V; AEC Category: Q200; AEC Grade: 0
R14 = CMP-0022510-4: RES, 5.23 k, 1%, 0.1 W, AEC-Q200 Grade 0, 0603; Manufacturer: Vishay-Dale; Power_W: 100mW; TempCo: 100 ppm/C; Value_Code: 5k23; Value: 5.23k; EIA_Code: E96; SizeX_mm: 1.6; SizeY_mm: 0.8; SizeZ_mm: 1; Value2: 0.1W; SizeArea_mm2: 1.28; AEC Qualified: Y; VDC_V: 75V; AEC Category: Q200; AEC Grade: 0
R16 = CMP-0022001-4: RES, 10.7 k, 1%, 0.1 W, AEC-Q200 Grade 0, 0603; Manufacturer: Vishay-Dale; Power_W: 100mW; TempCo: 100 ppm/C; Value_Code: 10k7; Value: 10.7k; EIA_Code: E96; SizeX_mm: 1.6; SizeY_mm: 0.8; SizeZ_mm: 1; Value2: 0.1W; SizeArea_mm2: 1.28; AEC Qualified: Y; VDC_V: 75V; AEC Category: Q200; AEC Grade: 0
R17 = CMP-0022036-4: RES, 130 k, 1%, 0.1 W, AEC-Q200 Grade 0, 0603; Manufacturer: Vishay-Dale; Power_W: 100mW; TempCo: 100 ppm/C; Value: 130k; EIA_Code: E96; SizeX_mm: 1.6; SizeY_mm: 0.8; SizeZ_mm: 1; Value2: 0.1W; SizeArea_mm2: 1.28; AEC Qualified: Y; VDC_V: 75V; AEC Category: Q200; AEC Grade: 0
R19 = CMP-0021990-4: RES, 100 k, 1%, 0.1 W, AEC-Q200 Grade 0, 0603; Manufacturer: Vishay-Dale; Power_W: 100mW; TempCo: 100 ppm/C; Value: 100k; EIA_Code: E96; SizeX_mm: 1.6; SizeY_mm: 0.8; SizeZ_mm: 1; Value2: 0.1W; SizeArea_mm2: 1.28; AEC Qualified: Y; VDC_V: 75V; AEC Category: Q200; AEC Grade: 0
R20 R35 = CMP-0022008-4: RES, 110 k, 1%, 0.1 W, AEC-Q200 Grade 0, 0603; Manufacturer: Vishay-Dale; Power_W: 100mW; TempCo: 100 ppm/C; Value: 110k; EIA_Code: E96; SizeX_mm: 1.6; SizeY_mm: 0.8; SizeZ_mm: 1; Value2: 0.1W; SizeArea_mm2: 1.28; AEC Qualified: Y; VDC_V: 75V; AEC Category: Q200; AEC Grade: 0
R21 = CMP-0022408-4: RES, 402 k, 1%, 0.1 W, AEC-Q200 Grade 0, 0603; Manufacturer: Vishay-Dale; Power_W: 100mW; TempCo: 100 ppm/C; Value: 402k; EIA_Code: E96; SizeX_mm: 1.6; SizeY_mm: 0.8; SizeZ_mm: 1; Value2: 0.1W; SizeArea_mm2: 1.28; AEC Qualified: Y; VDC_V: 75V; AEC Category: Q200; AEC Grade: 0
R23 R25 = CMP-0022544-4: RES, 64.9 k, 1%, 0.1 W, AEC-Q200 Grade 0, 0603; Manufacturer: Vishay-Dale; Power_W: 100mW; TempCo: 100 ppm/C; Value_Code: 64k9; Value: 64.9k; EIA_Code: E96; SizeX_mm: 1.6; SizeY_mm: 0.8; SizeZ_mm: 1; Value2: 0.1W; SizeArea_mm2: 1.28; AEC Qualified: Y; VDC_V: 75V; AEC Category: Q200; AEC Grade: 0
R24 = CMP-0025777-4: RES, 2.2, 5%, 0.1 W, AEC-Q200 Grade 0, 0603; Manufacturer: Vishay-Dale; Power_W: 100mW; TempCo: 200 ppm/C; Value_Code: 2R20; Value: 2.2; EIA_Code: E24; SizeX_mm: 1.6; SizeY_mm: 0.8; SizeZ_mm: 1; Value2: 0.1W; SizeArea_mm2: 1.28; AEC Qualified: Y; VDC_V: 75V; AEC Category: Q200; AEC Grade: 0
R30 = CMP-0022531-5: RES, 604, 1%, 0.1 W, AEC-Q200 Grade 0, 0603; Manufacturer: Vishay-Dale; Power_W: 100mW; TempCo: 100 ppm/C; Value_Code: 604R; Value: 604; EIA_Code: E96; SizeX_mm: 1.6; SizeY_mm: 0.8; SizeZ_mm: 1; Value2: 0.1W; SizeArea_mm2: 1.28; VDC_V: 75V; AEC Category: Q200; AEC Qualified: Y; AEC Grade: 0
R32 = CMP-0022114-4: RES, 1.13 k, 1%, 0.1 W, AEC-Q200 Grade 0, 0603; Manufacturer: Vishay-Dale; Power_W: 100mW; TempCo: 100 ppm/C; Value_Code: 1k13; Value: 1.13k; EIA_Code: E96; SizeX_mm: 1.6; SizeY_mm: 0.8; SizeZ_mm: 1; Value2: 0.1W; SizeArea_mm2: 1.28; AEC Qualified: Y; VDC_V: 75V; AEC Category: Q200; AEC Grade: 0
R34 = CMP-0022584-5: RES, 732, 1%, 0.1 W, AEC-Q200 Grade 0, 0603; Manufacturer: Vishay-Dale; Power_W: 100mW; TempCo: 100 ppm/C; Value_Code: 732R; Value: 732; EIA_Code: E96; SizeX_mm: 1.6; SizeY_mm: 0.8; SizeZ_mm: 1; Value2: 0.1W; SizeArea_mm2: 1.28; AEC Qualified: Y; VDC_V: 75V; AEC Category: Q200; AEC Grade: 0
T1 = CMP-0094349-1: Flyback Transformer, 5.5mOhm PRI, 1:0.25:1.25, 250kHz, 1500VAC, 27.1x26.42x14.5mm; Manufacturer: Pulse; Voltage_Isolation_Vrms: 1.5kV; DCR_ohm: 5.5m; SizeZ_mm: 14.5mm; AEC Qualified: No; Standoff Height: 0.15mm; Ind_H: 50µH; Rsec1_ohm: 85m
T2 = CMP-0030386-2: SMT Current Sense Tranformer; Manufacturer: Pulse Engineering; Green_Lifecycle: Not Set; Green_REACh: Incomplete; CompType: Transformer; Rsec1_ohm: 5.5
U1 = CMP-0031995-1: Advanced Active Clamp PWM Controller with Current-Mode Control, -40 to +125 degC, 20-pin TSSOP (PW), Green (RoHS & no Sb/Br); Manufacturer: Texas Instruments; Frequency(Max)(kHz): 1000; Regulated Outputs(#): 1; Rating: Catalog
U2 = CMP-0091995-1: General Purpose Amplifier 2 Circuit Rail-to-Rail 8-WSON (2x2); Manufacturer: Texas Instruments; Standoff Height: 0mm; Voltage Gain: 130dB; Min Supply Voltage: 2.7V; Output Current Per Channel: -20mA; Max Dual Supply Voltage: 18V; AEC Qualified: No; Max Supply Voltage: 36V; Gain Bandwidth: 1.2MHz; Input Bias Current: 0.000008uA; TaMin_C: -40°C; TJmax_C: +150°C; Nominal Supply Current: 110uA; Number Of Channels: 2; SizeZ_mm: 0.8mm; Min Dual Supply Voltage: 1.35V; Input Offset Voltage: 0.25mV; Response Time: 28us; TaMax_C: +125°C
U3 = CMP-0066949-1: 4A/4A Single Channel High-Speed Low-side Gate Driver, DBV0005A (SOT-23-5); Alternate PartNumber: UCC27519DBVT; Alternate Manufacturer: Texas Instruments; SizeAreaWB_mm2: 14.82; U/M: EA; SizeZ_mm: 1.45; SizeX_mm: 2.8; SizeY_mm: 2.9; SizeArea_mm2: 8.12; CompType: IC
U4 = CMP-0032746-2: Precision Micropower Shunt Voltage Reference, 1% accuracy, 5 V, 15 ppm / degC, 15 mA, -40 to 85 degC, 5-pin SC70 (DCK), Green (RoHS & no Sb/Br); Manufacturer: Texas Instruments; Min Iz for Regulation(uA): 79; Rating: Catalog; Initial Accuracy @ 25/deg C(%): 1; Iout/Iz(Max)(mA): 15; Temp Coeff(Max)(ppm/ degree C): 150; VO(V): 5; AEC Category: Q200; AEC Qualified: N; CompType: IC; SizeAreaWB_mm2: 9.3; SizeArea_mm2: 4.2; SizeX_mm: 2.1; SizeY_mm: 2.0; SizeZ_mm: 1.1
U5 = CMP-0006166-3: Optocoupler, 3.75 kV, 80-160% CTR, SMT; Manufacturer: Vishay-Semiconductor; CTR (Max): 160%; SizeAreaWB_mm2: 43.65; CTR (Min): 80%; SizeZ_mm: 2.3; SizeX_mm: 7; SizeY_mm: 2.85; SizeArea_mm2: 19.95; Voltage_Isolation_Vrms: 3.75kV

## Sheet PMP23123_RevE_SH2.SchDoc: Synchronous FET Drivers
size 431 x 279 mm; Date: Not shown in title block; ApprovedBy: Not shown in title block; CheckedBy: Not shown in title block; Author: Not shown in title block; CompanyName: Not shown in title block; DrawnBy: D Strasser; Engineer: Not shown in title block; Organization: Not shown in title block; Address1: Not shown in title block; Address2: Not shown in title block; Address3: Not shown in title block; Address4: Not shown in title block; DocumentNumber: 2; Revision: Use project parameter SCH_Rev; SheetNumber: 2; SheetTotal: 2; PageSetup: Record=PageOptions¦CenterHorizontal=True¦CenterVertical=True¦PrintScale=1.00¦XCorrection=1.00¦YCorrection=1.00¦PrintKind=0¦BorderSize=5000000¦LeftOffset=0¦BottomOffset=0¦Orientation=2¦PaperLength=1000¦PaperWidth=1000¦Scale=100¦PaperSource=15¦PrintQuality=600¦MediaType=1¦DitherType=10¦PaperKind=Letter¦PrintScaleMode=1
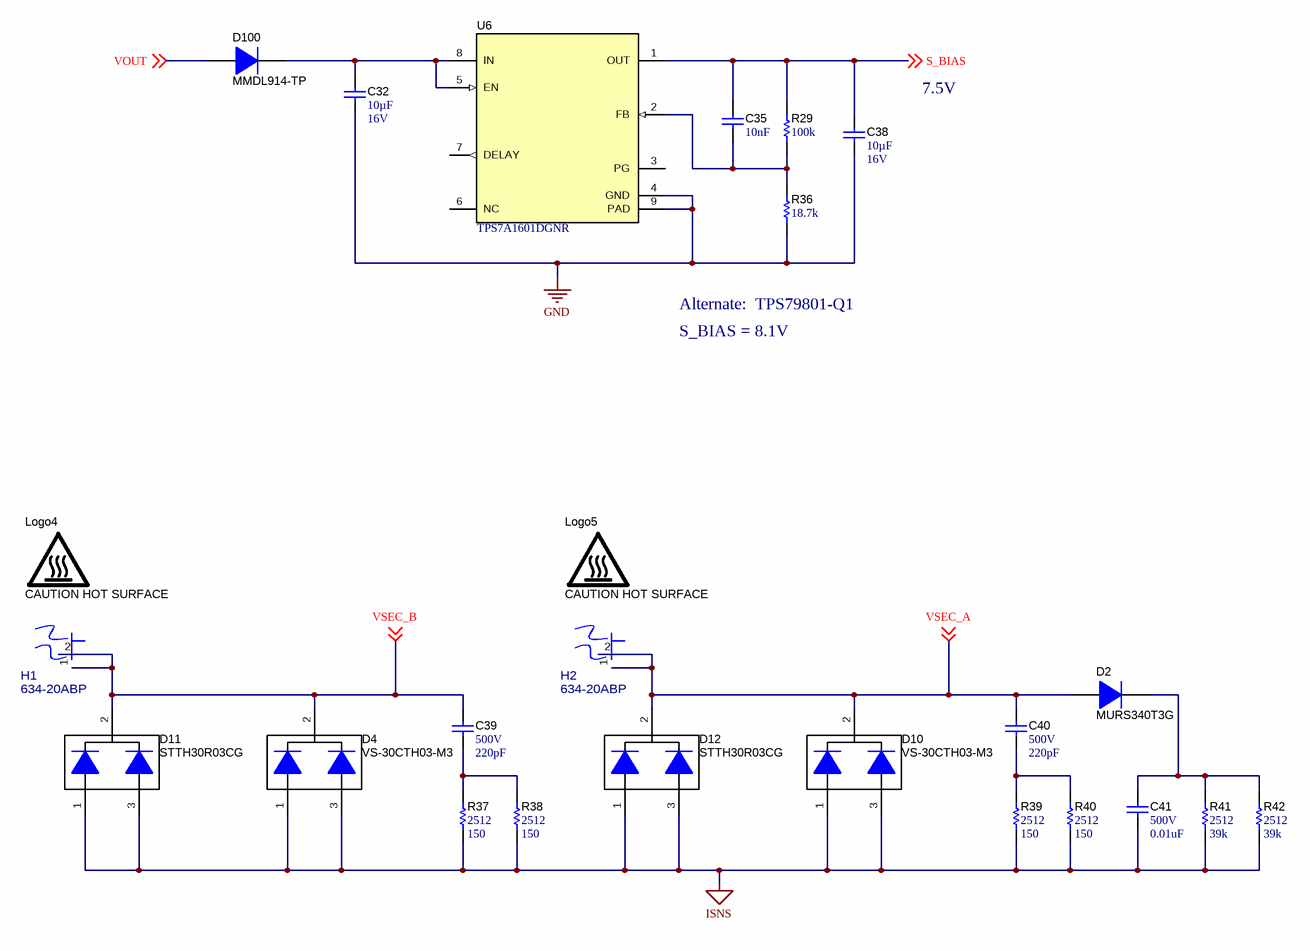
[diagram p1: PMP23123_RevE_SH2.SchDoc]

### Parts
C32  ValueDisplayed: 10µF  VDC_V: 16V  [1206]  (hidden comment: 885012208041)
C35  Cap_F: 10nF  [0603L]  (hidden comment: C0603C103K5RACTU)
C38  ValueDisplayed: 10µF  VDC_V: 16V  [1206]  (hidden comment: 885012208041)
C39  VDC_V: 500V  ValueDisplayed: 220pF  [1206]  (hidden comment: VJ1206Y221KXEAT5Z)
C40  VDC_V: 500V  ValueDisplayed: 220pF  [1206]  (hidden comment: VJ1206Y221KXEAT5Z)
C41  VDC_V: 500V  ValueDisplayed: 0.01uF  [1206]  (hidden comment: VJ1206Y103KXEAT5Z)
D2  MURS340T3G  [SMC]
D4  VS-30CTH03-M3  [TO-220AB]
D10  VS-30CTH03-M3  [TO-220AB]
D11  STTH30R03CG  [DDPAK]
D12  STTH30R03CG  [DDPAK]
D100  MMDL914-TP  [SOD-323]
H1  634-20ABP  [FP-634-20ABP_PTH_16MM26_16MM26-MFG]
H2  634-20ABP  [FP-634-20ABP_PTH_16MM26_16MM26-MFG]
Logo4  CAUTION HOT SURFACE  [IEC_HotSurface_Small]  (no BOM)
Logo5  CAUTION HOT SURFACE  [IEC_HotSurface_Small]  (no BOM)
R29  ValueDisplayed: 100k  [0603L]  (hidden comment: CRCW0603100KFKEA)
R36  ValueDisplayed: 18.7k  [0603L]  (hidden comment: CRCW060318K7FKEA)
R37  ValueDisplayed: 150  [2512]  (hidden comment: CRCW2512150RJNEG)
R38  ValueDisplayed: 150  [2512]  (hidden comment: CRCW2512150RJNEG)
R39  ValueDisplayed: 150  [2512]  (hidden comment: CRCW2512150RJNEG)
R40  ValueDisplayed: 150  [2512]  (hidden comment: CRCW2512150RJNEG)
R41  ValueDisplayed: 39k  [2512]  (hidden comment: CRCW251239K0JNEG)
R42  ValueDisplayed: 39k  [2512]  (hidden comment: CRCW251239K0JNEG)
U6  TPS7A1601DGNR  [DGN0008C_N]

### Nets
GND: C32.1 C38.1 R36.2 U6.4(GND) U6.9(PAD)
ISNS: C41.1 D4.1(A) D4.3(A) D10.1(A) D10.3(A) D11.1(A) D11.3(A) D12.1(A) D12.3(A) R37.2 R38.2 R39.2 R40.2 R41.2 R42.2
S_BIAS: C35.1 C38.2 R29.2 U6.1(OUT) ; off-sheet S_BIAS
VOUT: D100.2(A) ; off-sheet VOUT
VSEC_A: C40.2 D2.2(A) D10.2(K) D12.2(K) H2.1(MNT_1) H2.2(MNT_2) ; off-sheet VSEC_A
VSEC_B: C39.2 D4.2(K) D11.2(K) H1.1(MNT_1) H1.2(MNT_2) ; off-sheet VSEC_B
NetC32_2: C32.2 D100.1(K) U6.5(EN) U6.8(IN)
NetC35_2: C35.2 R29.1 R36.1 U6.2(FB)
NetC39_1: C39.1 R37.1 R38.1
NetC40_1: C40.1 R39.1 R40.1
NetC41_2: C41.2 D2.1(K) R41.1 R42.1

Not connected (* = marked no-connect by the designer): U6 3(PG) 6(NC) 7(DELAY)

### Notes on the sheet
- 7.5V
- Alternate:  TPS79801-Q1
- S_BIAS = 8.1V

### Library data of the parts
C32 C38 = CMP-0750070-1: CAP, CERM, 10 µF, 16 V,+/- 10%, X7R, 1206; Manufacturer: Wurth Elektronik; SizeArea_mm2: 5.12; SizeZ_mm: 1.35; Polarized: N; SizeAreaWB_mm2: 10.92; AEC Category: Q200; SizeX_mm: 3.2; TaMin_C: -55°C; U/M: EA; TaMax_C: 125°C; Value: 10uF; SizeY_mm: 1.6
C35 = CMP-0006854-4: as C30 on sheet PMP23123_RevE_SH1
C39 C40 = CMP-0009046-2: CAP, CERM, 220 pF, 500 V, +/- 10%, X7R, 1206; Manufacturer: Vishay-Vitramon; TaMin_C: -55°C; Polarized: N; SizeAreaWB_mm2: 10.92; Value1: Unknown; U/M: EA; Value: 220pF; TaMax_C: 125°C; SizeZ_mm: 1.35; SizeX_mm: 3.2; SizeY_mm: 1.6; SizeArea_mm2: 5.12; AEC Category: Q200
C41 = CMP-0009042-2: CAP, CERM, 0.01 uF, 500 V, +/- 10%, X7R, 1206; Manufacturer: Vishay-Vitramon; TaMin_C: -55°C; Polarized: N; SizeAreaWB_mm2: 10.92; Value1: Unknown; U/M: EA; Value: 0.01uF; TaMax_C: 125°C; SizeZ_mm: 1.35; SizeX_mm: 3.2; SizeY_mm: 1.6; SizeArea_mm2: 5.12; Cap_F: 10nF; AEC Category: Q200
D2 = CMP-0076962-2: Diode, Ultrafast, 400 V, 3 A, SMC; Manufacturer: ON Semiconductor; AEC Category: Q101; Io_A: 3A; RJC_CperW: 11.0; SizeArea_mm2: 50.5686; SizeX_mm: 8.13; SizeZ_mm: 2.6; SizeAreaWB_mm2: 83.2686; TJmax_C: 175°C; Green_REACh: Incomplete; Value2: 1.25V; Vr_V: 400V; Green_Lifecycle: Not Set; SizeY_mm: 6.22; Value: 400V
D4 D10 = CMP-0077080-4: Diode, Hyperafast, 300 V, 2x 15 A, TH; Manufacturer: Vishay; AEC Qualified: N; TJmax_C: 175°C; SizeY_mm: 4.5; RJC_CperW: 1.0; SizeX_mm: 10.2; Vr_V: 300V; SizeZ_mm: 19.4; Vf_V: 1.2V; Green_REACh: Incomplete; SizeAreaWB_mm2: 79.3; Green_Lifecycle: Not Set; Value: 300V; AEC Category: Q101; SizeArea_mm2: 45.9; Io_A: 30A; Type: Ultrafast
D11 D12 = CMP-0029029-4: Diode, Ultrafast, 300 V, 30 A, DDPAK; Manufacturer: STMicroelectronics; TJmax_C: 175°C; Vr_V: 300V; Green_Lifecycle: Not Set; Io_A: 30A; Value2: 1V; SizeX_mm: 15.245; SizeZ_mm: 4.445; SizeArea_mm2: 154.8892; Value: 300V; MFG_Status: TI_Obsolete; RJC_CperW: 2; SizeY_mm: 10.16; AEC Category: Q101; SizeAreaWB_mm2: 209.6992; Green_REACh: Incomplete
D100 = CMP-0029045-2: as D6 on sheet PMP23123_RevE_SH1
H1 H2 = CMP-0084930-1: Heat Sink TO-220, TO-218 Aluminum  Board Level, Vertical; Manufacturer: Wakefield-Vette; Mating Package: TO-220/TO-218; AEC Qualified: No; SizeZ_mm: 50.8mm
Logo4 Logo5 = CMP-0074837-2: as Logo3 on sheet PMP23123_RevE_SH1
R29 = CMP-0021990-4: as R19 on sheet PMP23123_RevE_SH1
R36 = CMP-0022098-4: RES, 18.7 k, 1%, 0.1 W, AEC-Q200 Grade 0, 0603; Manufacturer: Vishay-Dale; Power_W: 100mW; TempCo: 100 ppm/C; Value_Code: 18k7; Value: 18.7k; EIA_Code: E96; SizeX_mm: 1.6; SizeY_mm: 0.8; SizeZ_mm: 1; Value2: 0.1W; SizeArea_mm2: 1.28; AEC Qualified: Y; VDC_V: 75V; AEC Category: Q200; AEC Grade: 0
R37-R40 = CMP-0015884-3: RES, 150, 5%, 1 W, AEC-Q200 Grade 0, 2512; Manufacturer: Vishay-Dale; Power_W: 1W; TempCo: 200 ppm/C; Value_Code: 150R; Value: 150; EIA_Code: E24; SizeX_mm: 6.3; SizeY_mm: 3.2; SizeZ_mm: 0.71; SizeArea_mm2: 20.16; AEC Qualified: Y; VDC_V: 500V; AEC Grade: 0; AEC Category: Q200
R41 R42 = CMP-0015953-3: RES, 39 k, 5%, 1 W, AEC-Q200 Grade 0, 2512; Manufacturer: Vishay-Dale; Power_W: 1W; TempCo: 200 ppm/C; Value_Code: 39k0; Value: 39k; EIA_Code: E24; SizeX_mm: 6.3; SizeY_mm: 3.2; SizeZ_mm: 0.71; SizeArea_mm2: 20.16; AEC Qualified: Y; VDC_V: 500V; AEC Grade: 0; AEC Category: Q200
U6 = CMP-0035939-4: 60V, 5uA Iq, 100mA Low-Dropout (LDO) Voltage Regulator With Enable and Power Good, DGN0008C (VSSOP-8); Manufacturer: Texas Instruments; Alternate PartNumber: TPS7A1601DGNT; Iout(Max)(A): 0.1; Vout Adj(Min)(V): 1.2; Accuracy(%): 2; Vdo(Typ)(mV): 60; Power Good: TRUE; Vin(Min)(V): 3; Iq(Typ)(mA): 0.004; SubFamily: Single Channel LDO; Rating: Catalog; Vout Adj(Max)(V): 18.5; Eco-Plan: Green (RoHS & no Sb/Br); AEC Category: Q200; AEC Qualified: N; CompType: IC; SizeAreaWB_mm2: 23.6; SizeArea_mm2: 14.7; SizeX_mm: 4.9; SizeY_mm: 3.0; SizeZ_mm: 1.1; Green_Lifecycle: Active; Green_REACh: Passed

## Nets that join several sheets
GND: PMP23123_RevE_SH1 (25 pins), PMP23123_RevE_SH2 (5 pins)
ISNS: PMP23123_RevE_SH1 (7 pins), PMP23123_RevE_SH2 (15 pins)
S_BIAS: PMP23123_RevE_SH1 (6 pins), PMP23123_RevE_SH2 (C35.1 C38.2 R29.2 U6.1)
VOUT: PMP23123_RevE_SH1 (11 pins), PMP23123_RevE_SH2 (D100.2)
VSEC_A: PMP23123_RevE_SH1 (L2.2 T1.7), PMP23123_RevE_SH2 (6 pins)
VSEC_B: PMP23123_RevE_SH1 (T1.9), PMP23123_RevE_SH2 (5 pins)

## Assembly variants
001: not fitted C31 D7 D11 D12 R21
